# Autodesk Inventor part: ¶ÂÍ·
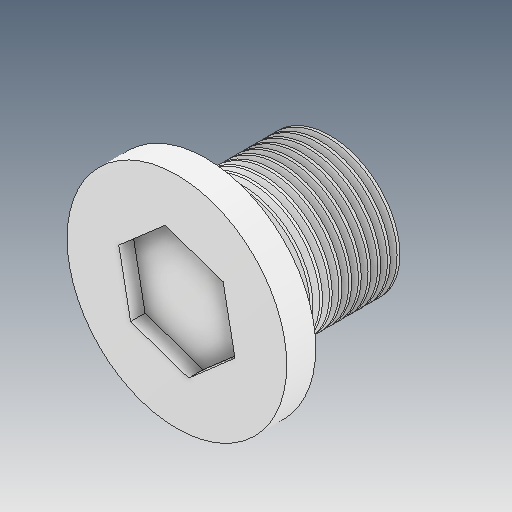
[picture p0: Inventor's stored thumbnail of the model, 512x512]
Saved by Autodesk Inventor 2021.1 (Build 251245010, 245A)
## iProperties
Created: 2021-05
Part Number: ¶ÂÍ·
Material: Ogólny
Document SubType Name: Modeling
Designer: user
Density: 1 g/cm^3
Appearance: Domyślna
Author: user
Revision Number: ÈÎºÎ
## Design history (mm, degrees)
feature "ÊäÈë1"
node "Bryła1"
